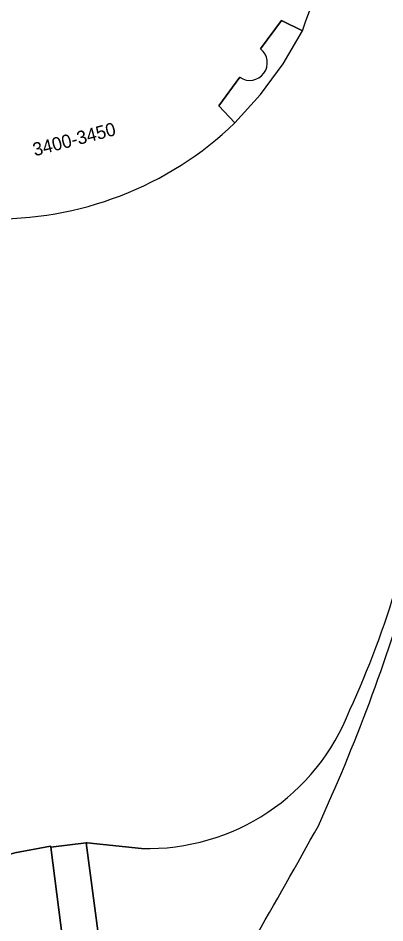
# Model space of a CAD drawing. Extents: x 155018 to 156648, y 383979 to 385733.
# Drawn here: x 156180 to 156207.6, y 384453.1 to 384521.3 of the extents above; entities that cross this region are included whole.
import ezdxf

# ---------------------------------------------------------------- set-up
doc = ezdxf.new("R2010")
doc.units = 0
for name, color, linetype in [('IMGEO_Erf', 7, 'Continuous'), ('IMGEO_Fietspad_open', 7, 'Continuous'), ('IMGEO_Groenvoorziening', 7, 'Continuous'), ('IMGEO_Muur', 7, 'Continuous'), ('IMGEO_Pand', 7, 'Continuous'), ('IMGEO_Pand_nummerreeks', 7, 'Continuous'), ('IMGEO_Pand_overbouw', 7, 'Continuous'), ('IMGEO_Rijbaan_lokaal_gesloten', 7, 'Continuous')]:
    doc.layers.add(name, color=color, linetype=linetype)

msp = doc.modelspace()

# ---------------------------------------------------------------- linework, layer by layer
at = {"layer": 'IMGEO_Erf'}
for points in [[(156201.441, 384520.353), (156199.849, 384521.115), (156198.279, 384518.984)], [(156196.711, 384516.847), (156195.134, 384514.69), (156196.348, 384513.409)], [(156121.442, 384514.007), (156163.051, 384466.066), (156172.857, 384455.946), (156172.771, 384455.862), (156172.915, 384455.68), (156173.267, 384455.967), (156173.436, 384456.485), (156179.774, 384458.427), (156182.449, 384458.923), (156182.48, 384458.856), (156185.149, 384459.164), (156185.209, 384459.171), (156189.306, 384458.751)]]:
    msp.add_lwpolyline(points, dxfattribs=at)
for centre, radius, start, end in [((156080.26, 384563.037), 128.479, 340.59617, 351.70676), ((156197.461, 384517.94), 1.326, 235.55375, 51.90836), ((156178.395, 384532.114), 25.926, 268.37713, 313.8244), ((156141.14, 384498.473), 70.261, 335.36522, 343.65994), ((156189.78, 384475.067), 16.322, 268.33702, 338.88295)]:
    msp.add_arc(centre, radius, start, end, dxfattribs=at)
at = {"layer": 'IMGEO_Fietspad_open'}
msp.add_lwpolyline([(156186.04, 384446.659), (156186.721, 384447.237), (156185.149, 384459.164), (156182.48, 384458.856), (156183.808, 384448.431), (156185.635, 384446.311)], close=True, dxfattribs=at)
at = {"layer": 'IMGEO_Groenvoorziening'}
msp.add_lwpolyline([(156189.306, 384458.751), (156185.209, 384459.171), (156185.149, 384459.164), (156186.721, 384447.237), (156186.04, 384446.659), (156189.846, 384442.257), (156200.24, 384430.238), (156200.548, 384429.882), (156202.847, 384427.226), (156203.331, 384426.668), (156203.695, 384426.247), (156207.298, 384422.086), (156207.743, 384421.572), (156210.467, 384418.425), (156210.651, 384418.213), (156219.006, 384408.567)], dxfattribs=at)
for centre, radius, start, end in [((156076.799, 384518.026), 138.376, 335.41761, 343.72975), ((156076.799, 384518.026), 138.376, 335.41761, 343.72975), ((156141.14, 384498.473), 70.261, 335.36522, 343.65994), ((156000.323, 384530.696), 226.958, 335.76153, 346.16484), ((156189.78, 384475.067), 16.322, 268.33702, 338.88295), ((155628.169, 384779.64), 657.179, 329.195604, 330.943024), ((155628.169, 384779.64), 657.179, 329.195604, 330.943024)]:
    msp.add_arc(centre, radius, start, end, dxfattribs=at)
at = {"layer": 'IMGEO_Muur'}
msp.add_arc((156000.323, 384530.696), 226.958, 335.76153, 346.16484, dxfattribs=at)
at = {"layer": 'IMGEO_Pand'}
for points in [[(156198.279, 384518.984), (156199.849, 384521.115), (156201.441, 384520.353)], [(156196.348, 384513.409), (156195.134, 384514.69), (156196.711, 384516.847)]]:
    msp.add_lwpolyline(points, dxfattribs=at)
for centre, radius, start, end in [((156080.26, 384563.037), 128.479, 340.59617, 351.70676), ((156197.461, 384517.94), 1.326, 235.55375, 51.90836), ((156178.395, 384532.114), 25.926, 268.37713, 313.8244)]:
    msp.add_arc(centre, radius, start, end, dxfattribs=at)
at = {"layer": 'IMGEO_Pand_overbouw'}
for points in [[(156201.441, 384520.353), (156199.849, 384521.115), (156198.279, 384518.984)], [(156196.711, 384516.847), (156195.134, 384514.69), (156196.348, 384513.409), (156198.273, 384515.552), (156199.976, 384517.874), (156201.441, 384520.353)]]:
    msp.add_lwpolyline(points, dxfattribs=at)
msp.add_arc((156197.461, 384517.94), 1.326, 235.55375, 51.90836, dxfattribs=at)
at = {"layer": 'IMGEO_Rijbaan_lokaal_gesloten'}
msp.add_lwpolyline([(156218.63, 384408.189), (156210.1, 384418.046), (156209.947, 384418.223), (156207.494, 384421.056), (156207.051, 384421.568), (156203.465, 384425.711), (156203.095, 384426.139), (156202.612, 384426.697), (156200.695, 384428.912), (156200.399, 384429.254), (156185.635, 384446.311), (156183.808, 384448.431), (156182.48, 384458.856), (156182.449, 384458.923), (156179.774, 384458.427), (156173.436, 384456.485), (156173.267, 384455.967), (156172.915, 384455.68), (156172.771, 384455.862), (156172.857, 384455.946), (156163.051, 384466.066), (156121.442, 384514.007)], dxfattribs=at)

# ---------------------------------------------------------------- texts
at = {"layer": 'IMGEO_Pand_nummerreeks'}
msp.add_text('3400-3450', height=1, rotation=14.65581, dxfattribs=at).set_placement((156181.268, 384510.889))

doc.saveas('drawing.dxf')
